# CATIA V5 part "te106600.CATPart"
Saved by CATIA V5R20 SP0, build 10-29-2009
Part number: 1
Definition: NONE
Nomenclature: 1
Source: Unknown
Description: PART-1-DESC
Bounding box of the stored display mesh (mm): x 0 to 600, y -5 to 5, z -5 to 5
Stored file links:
  C:\Users\Utente\Desktop\IO LAVORO\3D X SITO CF\CUMSA\3D files TE\te106600.CATPart
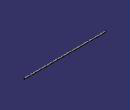
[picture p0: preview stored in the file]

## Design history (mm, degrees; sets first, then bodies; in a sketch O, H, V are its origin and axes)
Body1 "1" (main body)
  Solid1: solid without history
